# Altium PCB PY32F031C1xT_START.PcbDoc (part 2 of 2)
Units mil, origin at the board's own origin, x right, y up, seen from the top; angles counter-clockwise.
Board outline 1771.65 x 3929.06 mil, 2 copper layers (Top Layer, Bottom Layer), stack 21 mil thick; 137 components, 144 nets, 525 pads, 269 vias.
Unrouted connection lines stored in the file: 5.
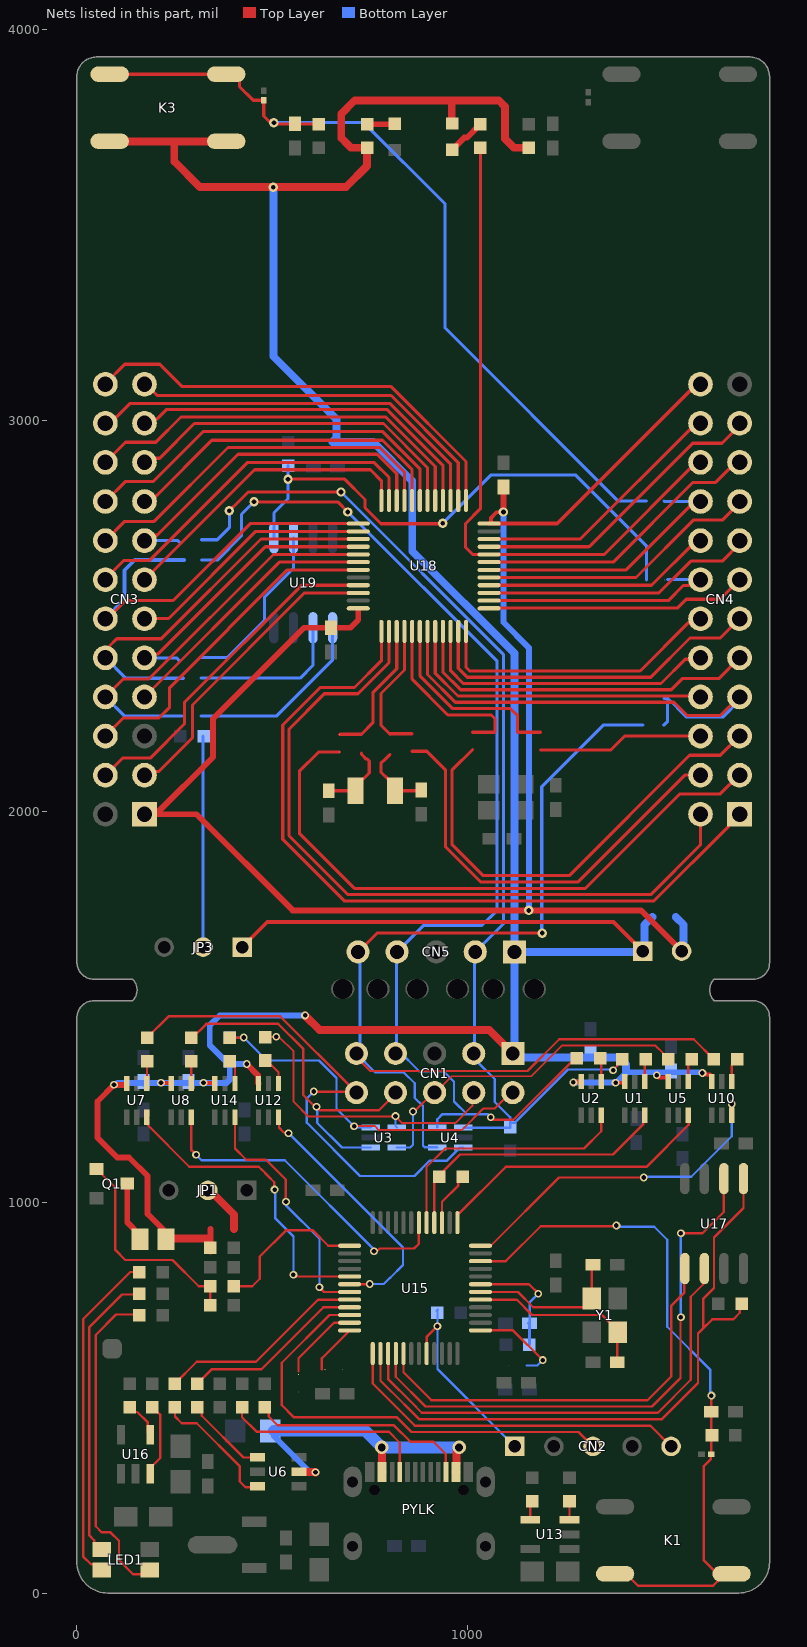
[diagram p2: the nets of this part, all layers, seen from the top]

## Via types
v1: diameter 19.68, hole 11.81, Top Layer to Bottom Layer, tented both sides, 116 vias
v2: diameter 24, hole 12, Top Layer to Bottom Layer, tented both sides, 99 vias
v3: diameter 19.68, hole 11.81, Top Layer to Bottom Layer, 42 vias
v4: diameter 35, hole 20, Top Layer to Bottom Layer, tented both sides, 8 vias
v5: diameter 30, hole 15, Top Layer to Bottom Layer, tented both sides, 2 vias
v6: diameter 40, hole 20, Top Layer to Bottom Layer, tented both sides, 2 vias

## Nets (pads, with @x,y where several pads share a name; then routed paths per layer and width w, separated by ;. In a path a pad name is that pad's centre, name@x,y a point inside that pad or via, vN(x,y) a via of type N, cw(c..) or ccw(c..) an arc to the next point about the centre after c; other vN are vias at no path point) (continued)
NetC32_1: C32.1 R54.2 Y3.2 | length 191.9
  Top Layer w8: C32.1@644,2052 Y3.2@713,2052 713,2064.8 729.67,2081.46 731.89,2081.46 747.91,2097.49 747.91,2128.31 743.22,2133 740,2133 728,2145 728,2149
NetC33_2: C33.2 R55.2 Y3.1 | length 186.4
  Top Layer w8: 800.54,2145 800.54,2144.54 789,2133 788.54,2133 777.52,2121.98 777.52,2100.14 796.2,2081.46 796.72,2081.46 813.39,2064.79 Y3.1@813.39,2052 879,2052 C33.2@881,2054
NetC34_2: C34.2 K3.3 K3.4 R56.1 R57.2 U21.1 | length 2162.7
  Top Layer w8: K3.4@85,3884.7 401.49,3884.7 415.99,3870.21 415.99,3853.01 450.72,3818.28 U21.1@478,3818.28 478,3778.17 492.11,3764.06 500.94,3764.06 v2(504,3761) ; v2@504,3767 513.02,3757.98 615.19,3757.98 R57.2@618,3760.8
  Bottom Layer w8: v2(504,3761) 734,3761 942,3553 942,3235.83 1384.84,2793 R56.1@1457.25,2793
NetCN4_3: CN4.3 R49.2 | length 1586.5
  Top Layer w8: R49.2@671.97,2150.97 617.97,2150.97 569,2102 569,1943 709.61,1802.39 1300.96,1802.39 1542.57,2044 1646,2044 1694,2092 CN4.3@1695,2092
NetCN4_4: CN4.4 R58.2 | length 1104.6
  Top Layer w8: R58.2@856.97,2152.97 895.03,2152.97 943.1,2104.9 943.1,1908.27 1032.37,1819 1056,1819 1282,1819 1555,2092 CN4.4@1595,2092
NetCN4_5: CN4.5 R59.2 | length 1180.8
  Top Layer w8: R59.2@1011.97,2156.97 959.1,2104.1 959.1,1914.9 1039,1835 1259,1835 1567,2143 1646,2143 CN4.5@1695,2192
NetCN4_6: CN4.6 R60.2 | length 423.9
  Top Layer w8: R60.2@1185.97,2155.97 1365.03,2155.97 1401.06,2192 CN4.6@1595,2192
NetJP3_2: JP3.2 R47.1 | length 539.2
  Bottom Layer w8: JP3.2@323,1652.81 R47.1@323,2192
NetLED1_2: LED1.2 R9.1 | length 846.1
  Top Layer w6: R9.1@160,710 157.67,712.33 100.33,712.33 48,660 48,171 63.8,155.2 85.86,155.2 107.53,133.53 107.53,84.16 143.82,47.87 175.08,47.87 LED1.2@186.02,58.82
NetLED1_3: LED1.3 R6.1 | length 884.3
  Top Layer w6: LED1.3@44.28,58.52 LED1.3@58.98,43.82 ; LED1.3@63.98,58.82 49.28,73.52 36.09,73.52 16,93.61 16,700.34 136.59,820.93 159.07,820.93 R6.1@160,820
NetLED1_4: LED1.4 R4.1 | length 755.1
  Top Layer w6: LED1.4@56.66,98.5 44.36,110.81 44.36,134.74 32,147.09 32,680.34 115.39,763.73 158.73,763.73 R4.1@160,765
NetLED_PB2_2: LED_PB2.2 R61.1 | length 98.9
  Top Layer w15: LED_PB2.2@960,3692 990.71,3722.71 997.72,3722.71 R61.1@1032,3756.99
NetLED_VDD*_1: LED_VDD*.1 R38.1 | length 70.4
  Top Layer w8: LED_VDD*.1@812,3757 LED_VDD*.1@813,3758
  Top Layer w15: R38.1@743,3757 LED_VDD*.1@812,3757
NetPYLK_A5: PYLK.A5 R1.2 | length 530.3
  Top Layer w6: R1.2@422.49,474.99 422.49,449.82 459.51,412.79 797.58,412.79 825.99,384.38 PYLK.A5@825.99,309.89
NetPYLK_B5: PYLK.B5 R3.1 | length 565.5
  Top Layer w6: R3.1@480,475 490.31,464.69 490.31,452.34 513.85,428.8 811.11,428.8 852.66,387.24 911.55,387.24 943.8,354.99 PYLK.B5@943.8,310.19
NetQ1_1: Q1.1 R19.1 R20.2 | length 559
  Top Layer w6: Q1.1@50,1084.8 51.97,1084.8 63.72,1073.06 63.72,1071.23 98.46,1036.49 98.46,877.34 123.86,851.94 244.45,851.94 311.61,784.78 R19.1@341.53,784.78 ; R20.2@341.52,735.88 R19.1@341.52,784.77
NetQ1_3: Q1.3 R15.1 | length 166.5
  Top Layer w6: Q1.3@125.49,1044.15 Q1.3@128.74,1047.4 ; R15.1@161.54,905 R15.1@161.54,910.91
  Top Layer w15: Q1.3@128.74,1047.4 128.74,948.28 161.54,915.49 R15.1@161.54,905
NetR2_1: R2.1 U1.4 | length 57.9
  Top Layer w6: U1.4@1452.23,1308.31 1452.23,1362.02 R2.1@1455.21,1365
NetR7_1: R7.1 U2.4 | length 57.8
  Top Layer w6: R7.1@1338.06,1365 1340.8,1362.27 U2.4@1340.8,1308.31
NetR10_1: R10.1 U5.4 | length 60.3
  Top Layer w6: U5.4@1563.66,1308.31 1563.66,1356.3 R10.1@1572.35,1365
NetR11_1: R11.1 U6.3 | length 332.9
  Top Layer w6: R11.1@250,475 250.77,474.23 250.77,451.69 268.41,434.05 306.8,434.05 416.24,324.61 416.24,285.87 431.63,270.48 459.74,270.48 U6.3@461.53,272.28
NetR12_1: R12.1 U6.1 | length 227.7
  Top Layer w6: R12.1@308.75,480 319.15,469.6 319.15,453.68 426,346.83 U6.1@471.97,346.83
NetR13_1: R13.1 U7.4 | length 59
  Top Layer w6: R13.1@173.55,1360 179.14,1354.41 U7.4@179.14,1303.31
NetR14_1: R14.1 U8.4 | length 60.8
  Top Layer w6: R14.1@280.94,1360.02 R14.1@290.82,1350.14 ; U8.4@292.86,1303.31 R14.1@292.86,1350.12
NetR18_1: R18.1 U10.4 | length 62.7
  Top Layer w6: U10.4@1675.08,1308.31 1675.08,1350.59 R18.1@1689.49,1365
NetR22_1: R22.1 U12.4 | length 75.3
  Top Layer w6: R22.1@481.63,1362.11 485.62,1362.11 515.71,1332.03 U12.4@515.71,1303.31
NetR24_2: R24.2 U13.4 | length 49.6
  Top Layer w6: U13.4@1160,187.5 1160,230 R24.2@1165,235
NetR25_2: R25.2 U13.3 | length 47.5
  Top Layer w6: U13.3@1260,187.5 R25.2@1260,235
NetR26_1: R26.1 U14.4 | length 62.8
  Top Layer w6: R26.1@391.2,1360.7 404.28,1347.62 U14.4@404.28,1303.31
NetR27_2: R27.2 U15.1 | length 237.7
  Top Layer w6: U15.1@1032.32,671.73 1115.61,671.73 v3(1191.46,595.88)
  Bottom Layer w6: R27.2@1150.03,582.03 1177.6,582.03 v3(1191.46,595.88)
NetR29_2: R29.2 U16.4 | length 96.1
  Top Layer w6: R29.2@135,475 147,463 154.44,463 181.5,435.94 181.5,411 U16.4@187.5,405
NetR30_2: R30.2 U16.3 | length 188.5
  Top Layer w6: U16.3@187.5,305 187.5,320 213.56,346.06 213.56,455.68 207,462.24 207,463 R30.2@195,475
NetR31_1: R31.1 U15.36 | length 129.6
  Top Layer w6: 626.21,571.75 626.21,600.26 U15.36@697.68,671.73
NetR33_1: R33.1 U15.35 | length 201.4
  Top Layer w6: 566.96,567.4 566.96,600.38 658,691.42 U15.35@697.68,691.42
NetR40_1: R40.1 R41.1 U19.1 | length 1390.7
  Top Layer w8: v2(540,2849.19) 684.68,2849.19 736.86,2797.01 736.86,2776.14 778,2735 935,2735 v2(936,2736)
  Bottom Layer w8: U19.1@504,2699 504,2763 540,2799 v2(540,2849.19) R40.1@540,2884 ; v2(936,2736) 1060,2860 1275,2860 1457.25,2677.75 R41.1@1457.25,2591
NetR42_1: R42.1 U19.2 | length 444.2
  Bottom Layer w8: R42.1@316.75,2393 385,2393 480,2488 480,2547 554,2621 U19.2@554,2699
NetR43_2: R43.2 U19.6 | length 396.6
  Bottom Layer w8: 317.03,2340.03 571.03,2340.03 604,2373 U19.6@604,2469
NetR44_2: R44.2 U19.5 | length 477.6
  Bottom Layer w8: R44.2@318.02,2243.03 510.03,2243.03 654,2387 U19.5@654,2469
NRST: CN4.7 R46.2 R53.2 U18.7 | length 1275.1
  Top Layer w8: U18.7@896.84,2459.68 896.84,2349.57 968.04,2278.36 1527.47,2278.36 1561.34,2244.5 1645.97,2244.5 1693.48,2292 CN4.7@1695,2292
  Bottom Layer w8: R53.2@1501.03,2220.03 1511,2230 1511,2281 ; R46.2@1502.03,2288.03 1511.97,2288.03 1558.64,2241.36 1653.32,2241.36 1695,2283.04 CN4.7@1695,2292
OSC32_IN: R49.1 R54.1 U18.3 | length 356.7
  Top Layer w8: R49.1@672,2195.75 673,2196.75 R54.1@728,2196.75 757,2225.75 757,2303 818.1,2364.1 U18.3@818.1,2459.68
OSC32_OUT: R55.1 R58.1 U18.4 | length 353.6
  Top Layer w8: U18.4@837.79,2459.68 837.79,2360.79 778,2301 778,2219.75 R55.1@801,2196.75 802,2197.75 R58.1@857,2197.75
OSC_IN: R48.2 R59.1 U18.5 | length 467.4
  Top Layer w8: U18.5@857.47,2459.68 857.47,2337.53 949,2246 1060,2246 1069.03,2236.97 R48.2@1069.03,2202.03 1068.75,2201.75 R59.1@1012,2201.75
OSC_OUT: R50.2 R60.1 U18.6 | length 507
  Top Layer w8: U18.6@877.16,2459.68 877.16,2346.62 961.78,2262 1109,2262 1127.34,2243.66 R50.2@1127.34,2201.56 1185.19,2201.56 R60.1@1186,2200.75
PA0: CN4.10 U18.10 | length 780.6
  Top Layer w8: U18.10@955.9,2459.68 955.9,2358.75 988.28,2326.36 1494.02,2326.36 1556.19,2388.53 1591.53,2388.53 CN4.10@1595,2392
PA1: CN4.11 U18.11 | length 885.5
  Top Layer w8: U18.11@975.58,2459.68 975.58,2364.98 998.2,2342.36 1467.7,2342.36 1568.18,2442.84 1645.84,2442.84 CN4.11@1695,2492
PA2: CN4.12 U18.12 | length 750.8
  Top Layer w8: U18.12@995.27,2459.68 995.27,2367.92 1004.82,2358.36 1440.6,2358.36 1563.71,2481.48 1584.48,2481.48 CN4.12@1595,2492
PA3: CN4.13 U18.13 | length 670.4
  Top Layer w8: U18.13@1054.8,2519.21 1535.86,2519.21 1558.55,2541.9 1644.9,2541.9 CN4.13@1695,2592
PA4: CN4.14 R41.2 U18.14 | length 646.9
  Top Layer w8: U18.14@1054.32,2538.42 1512.62,2538.42 1551.69,2577.49 1565.61,2577.49 1571.5,2583.38 1586.38,2583.38 CN4.14@1595,2592
  Bottom Layer w8: 1511,2592 CN4.14@1595,2592
PA5: CN4.15 U18.15 | length 700.9
  Top Layer w8: U18.15@1054.32,2558.1 1489.1,2558.1 1570.53,2639.53 1650.63,2639.53 1695,2683.9 CN4.15@1695,2692
PA6: CN4.16 U18.16 | length 588
  Top Layer w8: U18.16@1054.32,2577.79 1469.74,2577.79 1583.95,2692 CN4.16@1595,2692
PA7: CN4.17 U18.17 | length 723.6
  Top Layer w8: U18.17@1054.32,2597.47 1430.13,2597.47 1577.66,2745 1652,2745 1695,2788 CN4.17@1695,2792
PA8: CN3.20 U18.29 | length 1031.3
  Top Layer w8: CN3.20@73,2892 124.41,2943.41 201.7,2943.41 266.37,3008.08 790.02,3008.08 916.53,2881.57 U18.29@916.53,2794.32
PA9: CN3.19 U18.30 | length 896
  Top Layer w8: CN3.19@173,2892 183.52,2902.52 211.57,2902.52 300.42,2991.38 784.09,2991.38 896.84,2878.63 U18.30@896.84,2794.32
PA10: CN3.18 U18.31 | length 998.8
  Top Layer w8: CN3.18@73,2792 123.68,2842.68 194.5,2842.68 322.4,2970.58 782.26,2970.58 877.16,2875.68 U18.31@877.16,2794.32
PA11: CN3.17 U18.32 | length 859.1
  Top Layer w8: CN3.17@173,2792 187.88,2792 202.8,2806.92 203.59,2806.92 345.17,2948.5 781.71,2948.5 857.47,2872.75 U18.32@857.47,2794.32
PA12: CN3.16 U18.33 | length 962.2
  Top Layer w8: CN3.16@73,2692 122.07,2741.07 197.64,2741.07 386.68,2930.11 774.62,2930.11 837.79,2866.94 U18.33@837.79,2794.32
PA13: CN3.15 R51.2 U18.34 | length 918
  Top Layer w8: CN3.15@173,2692 183.52,2702.52 198.4,2702.52 201.51,2705.63 204.88,2705.63 412.19,2912.94 768.06,2912.94 818.1,2862.9 U18.34@818.1,2794.32
  Bottom Layer w8: CN3.15@173,2692 257.99,2692 262.99,2687
PA14: CN3.12 R52.2 U18.37 | length 1054.5
  Top Layer w8: CN3.12@73,2492 78.31,2492 124.87,2538.56 246.27,2538.56 442.98,2735.27 U18.37@719.68,2735.27
  Bottom Layer w10: CN3.12@73,2492 122,2541 122,2616 147.97,2641.97 R52.2@273.97,2641.97
PA15: CN3.11 U18.38 | length 639.3
  Top Layer w8: CN3.11@173,2492 173.58,2492.58 234.6,2492.58 457.6,2715.58 U18.38@719.68,2715.58
PB0: CN4.18 R56.2 U18.18 | length 706.5
  Top Layer w8: U18.18@1054.32,2617.16 1404.97,2617.16 1564.65,2776.84 1564.96,2776.84 1580.12,2792 CN4.18@1595,2792
  Bottom Layer w8: R56.2@1502.03,2793.03 1503.05,2792 CN4.18@1595,2792
PB1: CN4.19 U18.19 | length 746.4
  Top Layer w8: U18.19@1054.32,2636.84 1371.94,2636.84 1575.91,2840.81 1633.72,2840.81 1684.91,2892 CN4.19@1695,2892
PB2: CN4.20 R61.2 U18.20 | length 1743.9
  Top Layer w8: R61.2@1032,3696.99 1032,2773 994,2735 994,2675 1012.47,2656.53 U18.20@1054.32,2656.53 1349.01,2656.53 1584.48,2892 CN4.20@1595,2892
PB3: CN3.10 R43.1 U18.39 | length 1004.9
  Top Layer w8: CN3.10@73,2392 83.52,2402.52 83.52,2422.27 102.24,2440.98 215.88,2440.98 470.79,2695.9 U18.39@719.68,2695.9
  Bottom Layer w8: CN3.10@73,2392 125,2340 272.25,2340
PB4: CN3.9 R42.2 U18.40 | length 757.8
  Top Layer w8: CN3.9@173,2392 183.24,2402.24 208.27,2402.24 482.25,2676.21 U18.40@719.68,2676.21
  Bottom Layer w8: CN3.9@173,2392 254.73,2392 262.99,2383.74
PB5: CN3.8 R44.1 U18.41 | length 1013.2
  Top Layer w8: CN3.8@73,2292 119.25,2338.25 184.45,2338.25 502.73,2656.53 U18.41@719.68,2656.53
  Bottom Layer w8: CN3.8@73,2292 122,2243 268.25,2243
PB6: CN3.7 U18.42 | length 689.5
  Top Layer w8: CN3.7@173,2292 517.84,2636.84 U18.42@719.68,2636.84
PB7: CN3.6 U18.43 | length 852.6
  Top Layer w8: CN3.6@73,2192 73,2192.89 118.36,2238.25 209.6,2238.25 237.26,2265.92 237.26,2315.94 538.49,2617.16 U18.43@719.68,2617.16
PB8: CN3.4 U18.45 | length 880.3
  Top Layer w8: CN3.4@73,2092 116.5,2135.5 187.78,2135.5 275.36,2223.08 275.36,2278.33 574.82,2577.79 U18.45@719.68,2577.79
PB9: CN3.3 U18.46 | length 788.9
  Top Layer w8: CN3.3@173,2092 182.2,2101.2 209.31,2101.2 295.69,2187.58 295.69,2271.46 582.33,2558.1 U18.46@719.68,2558.1
PB10: CN4.21 U18.21 | length 775.1
  Top Layer w8: U18.21@1054.32,2676.21 1310.3,2676.21 1575.09,2941 1650.14,2941 1695,2985.86 CN4.21@1695,2992
PB11: CN4.22 U18.22 | length 663.3
  Top Layer w8: U18.22@1054.32,2695.9 1287.94,2695.9 1584.04,2992 CN4.22@1595,2992
PB12: CN3.24 U18.25 | length 1147.3
  Top Layer w8: CN3.24@73,3092 73,3093.6 122.51,3143.11 212.13,3143.11 269.52,3085.71 803.71,3085.71 995.27,2894.16 U18.25@995.27,2794.32
PB13: CN3.23 U18.26 | length 982.6
  Top Layer w8: CN3.23@173,3092 176.33,3092 205.27,3063.06 803.73,3063.06 975.58,2891.22 U18.26@975.58,2794.32
PB14: CN3.22 U18.27 | length 1061.5
  Top Layer w8: CN3.22@73,2992 85.18,2992 136.07,3042.89 800.46,3042.89 955.9,2887.45 U18.27@955.9,2794.32
PB15: CN3.21 U18.28 | length 926.8
  Top Layer w8: CN3.21@173,2992 183.52,3002.52 203.84,3002.52 228.21,3026.89 793.83,3026.89 936.21,2884.52 U18.28@936.21,2794.32
PF3: CN4.8 U18.8 | length 810.7
  Top Layer w8: U18.8@916.53,2459.68 916.53,2352.51 974.67,2294.36 1592.64,2294.36 CN4.8@1595,2292
PF4: CN4.9 U18.9 | length 915.3
  Top Layer w8: U18.9@936.21,2459.68 936.21,2355.81 981.66,2310.36 1519.91,2310.36 1548.51,2338.97 1641.97,2338.97 CN4.9@1695,2392
PF5: CN3.14 U18.35 | length 925.7
  Top Layer w8: CN3.14@73,2592 73,2594.42 119.15,2640.57 184.65,2640.57 435.36,2891.27 760.73,2891.27 798.42,2853.58 U18.35@798.42,2794.32
PF6: CN3.13 U18.36 | length 784.8
  Top Layer w8: CN3.13@173,2592 454.19,2873.19 750.94,2873.19 778.73,2845.4 U18.36@778.73,2794.32
PF8: CN4.1 U18.1 | length 2015.3
  Top Layer w8: U18.1@778.73,2459.68 778.73,2384.73 710.12,2316.12 622.12,2316.12 526.41,2220.41 526.41,1927.59 683.61,1770.39 1476.26,1770.39 1667.5,1961.63 1667.5,1964.5 CN4.1@1695,1992
PF9: CN4.2 U18.2 | length 1925
  Top Layer w8: U18.2@798.42,2459.68 798.42,2379.69 718.85,2300.12 632.74,2300.12 542.41,2209.79 542.41,1937.43 693.45,1786.39 1467.79,1786.39 1595,1913.6 CN4.2@1595,1992
PYLK_BOOT0: CN2.1 R28.1 U15.44 | length 514.7
  Top Layer w6: U15.44@894.53,612.68 894.53,655.07 v1(922.21,682.75)
  Bottom Layer w6: R28.1@923.26,724.4 920.49,721.63 922.21,719.9 v1(922.21,682.75) 922.21,572.79 CN2.1@1120,375
PYLK_KEY: C6.2 K1.1 K1.2 R16.1 U11.1 U15.10 | length 1798.2
  Top Layer w6: U15.10@1032.32,848.9 1097.14,848.9 1186.44,938.2 1378.2,938.2 v1(1380,940) ; K1.2@1376.55,49 1405.25,49 1435.5,18.75 1627.36,18.75 1639.02,30.41 1639.02,34.51 K1.1@1653.51,49 ; U11.1@1622.5,353.5 1622.5,403.5 C6.2@1622.5,463.5 1623,464 v1(1623,505) ; U11.1@1626.8,353.5 1625.06,353.5 1621.56,350 1621.56,342.45 1603,323.88 1603,191.77 1603,84.3 1638.3,49 K1.1@1653.51,49 ; K1.1@1674.55,49 K1.1@1653.51,49
  Bottom Layer w6: v1(1380,940) 1383.06,936.94 1392.62,936.94 1392.69,936.88 1476.64,936.88 1510,903.52 1510,681 1620.38,570.62 1620.38,507.62 v1(1623,505)
PYLK_NRST: C24.2 R36.1 U15.7 | length 298.5
  Top Layer w6: U15.7@1032.32,789.84 1156.36,789.84 v1(1180.4,765.8)
  Bottom Layer w6: C24.2@1158,690 1158,743.4 v1(1180.4,765.8)
  Bottom Layer w8: C24.2@1155.12,690 1157.6,687.52 R36.1@1157.6,635.62
PYLK_OSCIN: C19.2 U15.5 Y1.3 | length 465.6
  Top Layer w6: U15.5@1032.32,750.47 1125.05,750.47 1164.42,711.1 1343.11,711.1 1383.59,670.63 Y1.3@1383.59,666.69 1382.12,665.22 C19.2@1382.12,590
PYLK_OSCOUT: C25.2 U15.6 Y1.1 | length 399.8
  Top Layer w6: U15.6@1032.32,770.16 1127.99,770.16 1167.36,730.79 1297.03,730.79 1316.66,750.41 Y1.1@1316.66,753.31 1316.66,836.54 C25.2@1320.12,840
PYLK_SPI_CS: R35.1 U15.38 U17.1 | length 1667.6
  Top Layer w5: U15.38@776.42,612.68 776.42,543.62 837.66,482.38
  Top Layer w6: 837.66,482.38 875.95,444.09 1495.51,444.09 1588.88,537.47 1588.88,663.88 1601.77,676.77 ; R35.1@1700,740 1695.62,735.62 1695.62,716.69 1679.36,700.42 1625.42,700.42 1601.77,676.77 ; U17.1@1705,1060 1705,985 1629.69,909.69 1629.69,780.01 1601.77,752.09 1601.77,676.77
PYLK_SPI_MISO: U15.40 U17.2 | length 1437.2
  Top Layer w6: U15.40@815.79,612.68 815.79,553.3 891.8,477.3 1471,477.3 1543.9,550.2 1543.9,703.9 v1(1545,705) ; v1(1545,920) 1600,920 1655,975 U17.2@1655,1060
  Bottom Layer w6: v1(1545,705) v1(1545,920)
PYLK_SPI_MOSI: U15.41 U17.5 | length 1077.9
  Top Layer w6: U15.41@835.47,612.68 835.47,564.49 906.66,493.3 1459.42,493.3 1520.53,554.41 1520.53,735.09 1553.13,767.69 1553.13,828.13 U17.5@1555,830
PYLK_SPI_SCK: U15.39 U17.6 | length 1208.9
  Top Layer w6: U15.39@796.1,612.68 796.1,547.36 856.32,487.14 882.17,461.3 1486.07,461.3 1570.21,545.44 1570.21,758.06 1601.94,789.79 1601.94,826.94 U17.6@1605,830
SWD_SCK: CN2.5 U15.37 | length 906.8
  Top Layer w6: U15.37@756.73,612.68 756.73,535.75 864.48,428 1367,428 1467,428 CN2.5@1520,375
SWD_SDA: CN2.3 U15.34 | length 1172.2
  Top Layer w6: U15.34@697.68,711.1 646.11,711.1 524.05,589.04 524.05,480.71 555.57,449.2 818.75,449.2 855.95,412 1183,412 1283,412 CN2.3@1320,375
T_RESET: CN1.9 CN5.5 R18.2 R53.1 U4.4 | length 2815.6
  Top Layer w6: CN1.9@722.78,1362.78 750.2,1335.36 1152.91,1335.36 1233.99,1416.44 1578.06,1416.44 R18.2@1629.49,1365
  Top Layer w8: CN5.5@719.26,1639.56 767.7,1688 v2(1190,1688)
  Bottom Layer w6: CN1.9@715,1380 763.22,1331.78 836.02,1331.78 864.1,1303.69 864.1,1266.42 885.15,1245.37 885.15,1144.31 889.61,1139.85 921.09,1139.85 U4.4@921.54,1139.41
  Bottom Layer w8: CN1.9@715,1380 724.04,1389.04 CN5.5@724.04,1634.78 ; CN5.5@719.26,1639.56 CN5.5@724.15,1644.45 ; v2(1190,1688) 1189,1689 1189,2062.55 1346.45,2220 1448,2220
T_RESETa: U10.3 U15.12 | length 870.1
  Top Layer w6: U15.12@1032.32,888.27 1058.79,888.27 1233.47,1062.96 1321.53,1062.96 v1(1449.91,1062.96) ; v1(1674.82,1250.7) 1675.08,1250.44 U10.3@1675.08,1221.69
  Bottom Layer w6: v1(1449.91,1062.96) 1451.65,1064.7 1571.4,1064.7 1674.82,1168.11 v1(1674.82,1250.7)
T_RTCK_DTRa: U5.3 U15.13 | length 731.2
  Top Layer w6: U15.13@973.27,947.32 973.27,966.57 1096.7,1090 1456.99,1090 1565.18,1198.19 1565.18,1220.16 U5.3@1563.66,1221.69
T_RTCK_VCP_DTR: CN1.6 R10.2 U3.5 | length 868.3
  Top Layer w5: v1(859.81,1231.67) 863.24,1231.67 911.57,1280 CN1.6@915,1280 916.63,1280 958.49,1321.86 1161.73,1321.86 1240.3,1400.44 1479.98,1400.44 1500.35,1380.07 1500.35,1377 R10.2@1512.35,1365
  Bottom Layer w6: U3.5@818.46,1139.41 852.51,1139.41 859.81,1146.71 v1(859.81,1231.67)
T_TCK_SWCLK: CN1.7 CN5.4 R7.2 R52.1 U4.5 | length 2940.6
  Top Layer w6: CN1.7@820,1390 CN1.7@821.35,1391.35 ; v1(1058.5,1217.32) 1065.14,1210.69 1116.96,1210.69 1271.28,1365 R7.2@1278.06,1365
  Top Layer w8: v2(453,2791) 666.98,2791 v2(692.99,2764.99)
  Bottom Layer w6: CN1.7@822.5,1387.5 875.47,1334.53 937.65,1334.53 964.6,1307.57 964.6,1257.54 997.14,1225 ; U4.5@921.54,1190.59 921.54,1211.54 935,1225 997.14,1225 ; v1(1058.5,1217.32) 1050.82,1225 997.14,1225
  Bottom Layer w8: R52.1@318.75,2642 359,2642 421,2704 421,2759 v2(453,2791) ; v2(692.99,2764.99) 1074.75,2383.23 1074.75,1746.75 1035,1707 886,1707 CN5.4@819,1640 ; CN1.7@815,1380 817.79,1382.79 CN5.4@817.79,1638.1
T_TCK_SWCLKa: U2.3 U15.17 | length 668.1
  Top Layer w5: U15.17@894.53,947.32 894.53,1089.76 941.77,1137
  Top Layer w6: 941.77,1137 1047.62,1137 1297.43,1137 1341.41,1180.98 1341.41,1221.08 U2.3@1340.8,1221.69
T_TDI_VCP_TX: CN1.4 R22.2 U3.4 | length 783.1
  Top Layer w5: R22.2@481.63,1422.11 517.9,1422.11 554.54,1385.48 554.54,1256.62 592.29,1218.86 v1@815,1218.86 ; R22.2@481.63,1425.11 R22.2@483.13,1423.61 ; v1@815.02,1218.86 831.78,1202.11 967.76,1202.11 1011.56,1245.9 1011.56,1276.56 CN1.4@1015,1280
  Bottom Layer w5: v1@815.06,1219.94 815.06,1194 U3.4@818.46,1190.59
  other v1: 815,1220
  other v3: 509.96,1422.98
T_TDI_VCP_TXa: U12.3 U15.30 | length 672.4
  Top Layer w6: U12.3@515.71,1216.69 516.93,1215.47 516.93,1190.37 529.24,1178.06 539.56,1178.06 v1(541.31,1176.31) ; U15.30@697.68,789.84 748.02,789.84 v1(748.76,790.58)
  Bottom Layer w6: v1(541.31,1176.31) 834.09,883.53 834.09,838.92 801.56,806.38 800.71,806.38 784.91,790.58 v1(748.76,790.58)
T_TDO_SWO: CN1.10 R13.2 U4.3 | length 1321
  Top Layer w6: R13.2@179.66,1420.08 234.47,1474.9 520.1,1474.9 CN1.10@708.51,1286.49 ; v1(605.87,1282.75) 606.54,1282.08 704.1,1282.08 CN1.10@708.51,1286.49 ; CN1.10@715,1280 CN1.10@708.51,1286.49
  Bottom Layer w6: v1(605.87,1282.75) 587.83,1264.72 587.83,1203.17 724.14,1066.86 863.29,1066.86 902.42,1105.99 946.45,1105.99 979.88,1139.41 U4.3@988.46,1139.41 U4.3@986.15,1137.1
T_TDO_SWOa: U7.3 U15.29 | length 807.7
  Top Layer w6: U7.3@179.14,1216.69 179.14,1198.86 287.46,1090.54 465.08,1090.54 471.63,1084 472.01,1084 489,1067.01 489,1066.63 504.93,1050.7 504.93,1032.69 v1(505.62,1032) ; v1(553.88,814.33) 558.68,809.53 641.55,809.53 U15.29@697.68,809.53
  Bottom Layer w6: v1(505.62,1032) 506.95,1030.68 506.95,958.93 553.88,912 v1(553.88,814.33)
T_TMS_SWDIO: CN1.3 CN5.2 R2.2 R5.2 R51.1 U4.1 | length 2763.3
  Top Layer w6: CN1.3@1019.37,1366.19 CN1.3@1025.56,1360 ; v1@1371.62,1338.31 1382.21,1348.9 1382.21,1352 R2.2@1395.21,1365
  Top Layer w8: v2(390,2768) 414.53,2792.53 438.27,2816.27 v2(675.65,2816.27)
  Bottom Layer w6: U4.1@988.77,1190.29 R5.2@1109,1190.29 ; CN1.3@1015,1380 CN1.3@1017.13,1382.13 ; CN1.3@1023.59,1359.7 1068.86,1314.42 1068.86,1256.14 1108.1,1216.9 R5.2@1108.1,1203 ; R5.2@1109,1191 1108.1,1191.9 R5.2@1108.1,1203 ; v1(1371.43,1337.07) 1369.25,1339.25 1256.25,1339.25 1122,1205 1122,1204 1121,1203 R5.2@1108.1,1203
  Bottom Layer w8: R51.1@318.75,2694 359,2694 390,2725 v2(390,2768) ; v2(675.65,2816.27) 1091,2400.92 1091,1711.3 1017.13,1637.43 CN1.3@1017.13,1382.13
T_TMS_SWDIOa: R32.1 U1.3 U15.16 | length 723.8
  Top Layer w6: U15.16@914.21,947.32 R32.1@914.21,1067.37 ; R32.1@927.46,1064.37 927.46,1068.99 980.12,1121.65 1036.7,1121.65 1371.22,1121.65 1448.34,1198.77 1448.34,1217.8 U1.3@1452.23,1221.69
T_TMS_SWDIOa_OUT: R32.2 U15.15 | length 143.2
  Top Layer w6: U15.15@933.9,947.32 933.9,1000.64 975.82,1042.56 R32.2@975.82,1073.16
T_TRST_RTSa: U8.3 U15.18 | length 840.3
  Top Layer w6: U8.3@292.86,1216.69 292.86,1132.86 v1(304.82,1120.9) ; v1(759.92,874.35) 763.83,870.44 774.54,881.16 862.39,881.16 874.84,893.6 U15.18@874.84,947.32
  Bottom Layer w6: v1(304.82,1120.9) 318.81,1106.91 531.65,1106.91 759.92,878.64 v1(759.92,874.35)
T_TRST_VCP_RTS: CN1.8 R14.2 U3.1 | length 935
  Top Layer w6: R14.2@292.3,1420.1 295.54,1420.1 331.24,1455.8 515.25,1455.8 578.58,1392.47 578.58,1274.56 609.4,1243.73 v1(612.86,1243.73) 621.6,1235 772.67,1235 820,1282.33 CN1.8@820,1290
  Bottom Layer w6: v1(612.86,1243.73) 615,1241.6 615,1202.6 678.19,1139.41 U3.1@751.54,1139.41
T_VCP_RX: CN1.2 R23.1 R26.2 U3.3 | length 1000.9
  Top Layer w5: v1(708.97,1193.74) 710.23,1195 761.42,1195 772.45,1183.97 983.91,1183.97 1039.3,1239.36 1069.36,1239.36 CN1.2@1120,1290
  Top Layer w6: R26.2@391.2,1420.7 426.7,1420.7 v3(427,1421) ; R26.2@391.2,1431.85 R26.2@391.32,1431.97
  Bottom Layer w6: R23.1@391,1420 392,1421 v3(427,1421) 485.72,1362.28 619.26,1362.28 664.05,1317.5 664.05,1238.66 v1(708.97,1193.74) 708.23,1193 708.23,1191.77 750.36,1191.77 U3.3@751.54,1190.59
T_VCP_RXa: U14.3 U15.31 | length 636
  Top Layer w6: U14.3@404.28,1216.69 404.28,1137.29 433.27,1108.3 483.54,1108.3 534.4,1057.43 534.4,1001.38 v1(535,1000.78) ; v1(620.4,781.75) 631.99,770.16 U15.31@697.68,770.16
  Bottom Layer w6: v1(535,1000.78) 535,991.42 620.4,906.02 v1(620.4,781.75)
TVDD: C12.2 C13.2 C14.2 C15.2 CN1.1 CN5.1 JP2.1 JP3.1 K3.1 K3.2 LED_PB2.1 R15.2 R17.2 R23.2 R34.2 R37.1 R38.2 R39.1 R45.1 U1.6 U2.6 U5.6 U7.6 U8.6 U10.6 U12.6 U14.6 | length 8731.3
  Top Layer w6: U8.6@241.67,1303.31 U8.6@244.56,1306.2 ; U14.6@353.1,1303.31 U14.6@355.99,1306.2
  Top Layer w10: v1(215,1305) 239.98,1305 U8.6@241.67,1303.31 ; v3@325,1305 351.41,1305 U14.6@353.1,1303.31 ; JP3.1@423,1652 487,1716 1373,1716 JP2.1@1447,1642 ; v3(1377.88,1305.09) 1399.07,1305.09 1399.16,1305 1401.05,1306.89 U1.6@1401.05,1308.31 ; v1(1483.29,1324.06) 1488.61,1318.74 1512.47,1318.74 U5.6@1512.47,1308.31 ; v1@1608.68,1326.1 1618.91,1326.1 1623.9,1321.1 U10.6@1623.9,1308.31
  Top Layer w12: v1@1270.9,1306.9 U2.6@1289.01,1306.9
  Top Layer w15: v1(95,1300) 52.5,1257.5 52.5,1164.78 103.07,1114.2 133.42,1114.2 180.53,1067.09 180.53,969.95 220.52,929.96 220.52,912.95 R15.2@228.46,905 R15.2@230.24,906.78 ; v1@95.63,1299.37 U7.6@127.35,1299.37 ; 338.07,906.78 342.08,902.77 ; R17.2@342.08,874.02 342.08,902.77 ; 342.08,931.52 342.08,902.77 ; v3(434.28,1353.05) 462.84,1324.49 462.84,1305 U12.6@464.53,1303.31 ; v1(1270,1306) v1@1270.9,1306.9
  Top Layer w20: K3.2@85,3713 249,3713 ; R15.2@230.24,906.78 338.07,906.78 ; K3.1@383,3713 249,3713 ; v3(583.63,1477.38) 620.91,1440.1 1054.9,1440.1 CN1.1@1115,1380 ; LED_PB2.1@960,3759 959,3760 959,3818 ; R45.1@1156,3697 1118,3697 1095,3720 1095,3802 1079,3818 959,3818 ; 249,3713 249,3662 315,3596 v2(502.64,3596) 688,3596 742,3650 742,3696 R38.2@743,3697 701,3697 692.03,3705.97 676,3722 676,3783 711,3818 959,3818
  Bottom Layer w15: v1(95,1300) 98.79,1300 103.67,1304.88 C15.2@168.87,1304.88 ; C15.2@170,1303.74 C15.2@168.87,1304.88 ; v1@214.88,1304.88 C15.2@168.87,1304.88 ; v1(215,1305) v3(323.77,1305) 383,1305 391,1313 R23.2@391,1360 380.76,1360 340,1400.76 340,1452 365.38,1477.38 v3(583.63,1477.38) ; R23.2@391,1353.05 v3(434.28,1353.05) ; v1@1270.38,1305.62 v3@1377.36,1305.62 ; v3(1377.88,1305.09) 1379.15,1305.09 1381.49,1307.43 1382.09,1307.43 1406.58,1331.92 ; 1404.72,1331.92 1598.08,1331.92 v1(1600,1330)
  Bottom Layer w20: v2(502.64,3596) 502.64,3163.36 664,3002 664,2954.25 R39.1@653.75,2944 662,2944 758,2944 858,2844 858,2665.04 1119.26,2403.78 1119.26,1639.56 1449.44,1639.56 1452,1637 1452,1709 1472,1729 ; CN1.1@1118.94,1383.94 CN5.1@1118.94,1639.24 ; CN1.1@1122.04,1388.26 1143.46,1370 1386.9,1370 1404.72,1352.18 1404.72,1331.92
TVDD*: JP1.2 R34.1 | length 129
  Top Layer w20: JP1.2@335,1030 339.73,1030 402.08,967.65 402.08,931.52
TVDD_DISCHARGE_EN: R19.2 U15.25 | length 404.9
  Top Layer w6: R19.2@401.53,784.78 448.51,784.78 467.48,803.75 467.48,860.55 534.58,927.66 603.61,927.66 643,888.27 U15.25@697.68,888.27
USB_DM: R11.2 U15.32 | length 536.9
  Top Layer w6: R11.2@250,535 306.4,591.4 458.28,591.4 617.36,750.47 U15.32@697.68,750.47
USB_DP: R12.2 U15.33 | length 471.3
  Top Layer w6: R12.2@307.5,535 344.45,571.95 471.73,571.95 630.56,730.79 U15.33@697.68,730.79
VBUS_PYLK: F1.1 PYLK.A4 PYLK.A9 PYLK.B4 PYLK.B9 U6.5 | length 779.7
  Top Layer w10: PYLK.A4@774.81,309.89 PYLK.B9@786.62,309.89 ; PYLK.B4@963.78,309.88 PYLK.A9@975.6,309.88
  Top Layer w20: U6.5@568.15,310 568.98,309.17 609.58,309.17 v1(610.2,308.55) ; PYLK.B9@780.78,327.94 v4@780.78,371.72 ; PYLK.A9@971.19,329.42 v4@971.19,363.23
  Bottom Layer w15: F1.1@504.16,400.84 504.89,400.84 513.76,391.97 513.76,391.24 595.55,309.45 609.31,309.45 v1(610.2,308.55)
  Bottom Layer w30: F1.1@504.16,415 737.5,415 v4(780,372.5) v4(977.62,372.5)
VDD: C26.1 C27.2 CN3.1 CN4.24 JP2.2 R37.2 U18.24 U18.48 | length 4276.4
  Top Layer w10: U18.24@1054.32,2735.27 U18.24@1058.44,2735.27 ; v2(1091,2765) 1090.41,2764.41 1073.41,2764.41 1058.73,2749.73 1058.73,2735.56 U18.24@1058.44,2735.27 ; CN4.24@1595,3092 1585.43,3092 1228.7,2735.27 U18.24@1058.44,2735.27
  Top Layer w15: CN3.1@173,1992 CN3.1@202,1992 ; U18.48@719.78,2517 719.78,2488.78 700,2469 C26.1@650,2469 581,2469 348,2236 348,2138 CN3.1@202,1992 ; v2(1091,2765) 1091.5,2765.5 1091.5,2825.5 C27.2@1092,2826 ; JP2.2@1546.26,1642.74 1442.88,1746.12 1156.12,1746.12 v2(1156,1746) 1155.88,1746.12 551.88,1746.12 306,1992 CN3.1@202,1992
  Bottom Layer w15: v2(1091,2765) 1091,2483 1156,2418 v2(1156,1746)
  Bottom Layer w20: 1532,1729 1552,1709 JP2.2@1552,1637
pads on no net: PYLK. PYLK.A8 PYLK.B8 U15.42 U15.45

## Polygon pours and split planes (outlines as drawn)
GND on Bottom Layer "NONET_L-01_P-001" (solid, remove dead copper, pour order 3): 8.64,3929.06 1773.49,3929.06 1773.49,0 0,0
GND on Top Layer "NONET_L-01_P-001" (solid, remove dead copper, pour order 4): 8.64,3929.06 1773.49,3929.06 1773.49,0 0,0

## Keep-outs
Keep-Out Layer:
  lines w8: 0,78.74 ccw(c78.74,78.74) 78.74,0 1692.91,0 ccw(c1692.91,78.74) 1771.65,78.74 1771.65,1473.35 ccw(c1730,1473.35) 1730,1515 1630,1515 cw(c1657.5,1542.5) 1630,1570 1730,1570 ccw(c1730,1611.65) 1771.65,1611.65 1771.65,3855.75 1771.65,3879.06 ccw(c1721.65,3879.06) 1721.65,3929.06 1692.91,3929.06 78.74,3929.06 50,3929.06 ccw(c50,3879.06) 0,3879.06 0,3859.09 0,1615 ccw(c43.75,1613.75) 42.5,1570 142.5,1570 cw(c115,1542.5) 142.5,1515 42.5,1515 ccw(c43.75,1471.25) 0,1470 0,78.74 ; 215,1515 cw(c242.5,1542.5) 215,1570 565,1570 585,1570 cw(c557.5,1542.5) 585,1515 565,1515 215,1515 ; 1260,1515 cw(c1287.5,1542.5) 1260,1570 1280,1570 1560,1570 cw(c1532.5,1542.5) 1560,1515 1280,1515 1260,1515

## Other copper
Top Layer:
  pour cut-out: 1655,1370 1665,1370 1665,1360 1655,1360
  pour cut-out: 275,490 285,490 285,480 275,480
  pour cut-out: 275,525 285,525 285,515 275,515
  pour cut-out: 330,525 335.5,525 335.5,503 330,503
  pour cut-out: 330,490 340,490 340,480 330,480
  region net 5V_USB_CHGR: 385,235 395,245 420,245 465,200 510,200 530,180 660,180 660,120 515,120 515,140 490,165 435,165 400,200 385,215
  region net 3V3_PYLK: 240,315 290,315 310,295 355,295 360,290 360,250 345,235 345,165 362.5,147.5 355,140 293.39,140 293.39,153.49 305,165.1 305,230 280,255 240,255
  region net 3V3_PYLK: 1095,155 1105,165 1125,165 1135,155 1135,130 1140,125 1185,125 1190,120 1190,105 1185,100 1130,100 1095,135
  region net 3V3_USB_PYLK: 1227.5,120 1300,120 1315,135 1335,135 1345,125 1345,105 1330,90 1315,90 1290,65 1290,25 1225,25 1225,118.33
  pour cut-out: 390,495 400,495 400,485 390,485
  pour cut-out: 445,495 455,495 455,485 445,485
  pour cut-out: 1627.43,1037 1637.43,1037 1637.43,1027 1627.43,1027
  pour cut-out: 1675,1075 1685,1075 1685,1065 1675,1065

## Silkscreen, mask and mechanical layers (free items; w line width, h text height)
Top Overlay:
  drawing of 1057 lines, arcs and shapes, not listed
  text "USER_PB0" at 85,3605.66 h60
  text "NRST" at 1476.78,3595.64 h60
  text "PY32F031-START V2.0" at 656,3242.17 h65
  text "2025-05" at 809.95,3173.47 h65
  text "24" at 1573.96,3169 h50
  text "23" at 1682.96,3165.54 h50
  text "25" at 49.96,3164.54 h50
  text "26" at 147.96,3163.54 h50
  text "B13" at 390,3081.62 h50
  text "B12" at 246,3081.08 h50
  text "GND" at 1425,3074.62 h50
  text "VDD" at 1281,3074.08 h50
  text "B14" at 246,2979.57 h50
  text "B15" at 390,2980.1 h50
  text "B11" at 1281,2972.57 h50
  text "B10" at 1425,2973.1 h50
  text "A8" at 245.96,2880.3 h50
  text "A9" at 389.96,2880.3 h50
  text "B2" at 1281,2872.77 h50
  text "B1" at 1425,2872.77 h50
  text "A10" at 245.96,2778.89 h50
  text "A11" at 389.96,2778.36 h50
  text "B0" at 1281,2771.89 h50
  text "A7" at 1424.96,2771.36 h50
  text "A13" at 389.96,2677.91 h50
  text "A12" at 245.96,2677.38 h50
  text "A6" at 1280.96,2670.91 h50
  text "A5" at 1424.96,2670.91 h50
  text "F5" at 246,2578.11 h50
  text "F6" at 390,2578.11 h50
  text "A4" at 1280.96,2570.58 h50
  text "A3" at 1424.96,2571.11 h50
  text "A14" at 245.96,2475.6 h50
  text "A15" at 389.96,2476.14 h50
  text "A2" at 1280.96,2468.6 h50
  text "A1" at 1424.96,2468.6 h50
  text "B3" at 246,2376.23 h50
  text "B4" at 390,2375.69 h50
  text "A0" at 1280.96,2369.23 h50
  text "F4" at 1425,2368.69 h50
  text "B5" at 246,2275.89 h50
  text "B6" at 390,2275.89 h50
  text "F3" at 1281,2268.89 h50
  text "F2" at 1425,2268.36 h50
  text "B7" at 246,2173.84 h50
  text "BOOT0" at 390,2174.38 h50
  text "F1" at 1281,2166.84 h50
  text "F0" at 1425,2167.38 h50
  text "B8" at 246,2074.58 h50
  text "B9" at 390,2074.58 h50
  text "F10" at 1425,2067.58 h50
  text "F11" at 1281,2067.04 h50
  text "GND" at 246,1973.06 h50
  text "VDD" at 390,1972.53 h50
  text "F9" at 1281,1966.06 h50
  text "F8" at 1425,1966.06 h50
  text "1" at 1689,1893 h50
  text "2" at 1579.96,1892 h50
  text "48" at 151,1890.54 h50
  text "47" at 50,1888 h50
  text "GND" at 146,1725.54 h50
  text "BOOT0" at 259,1725.54 h50
  text "VDD*" at 426,1725 h50
  text "VDD*" at 1100,1710.51 h45
  text "NRST" at 630,1710.48 h45
  text "SWC" at 760,1710.48 h45
  text "GND" at 870,1710.48 h45
  text "SWD" at 985,1710.48 h45
  text "VDD*" at 1377,1698 h45
  text "VDD" at 1507,1698 h45
  text "IDD" at 1607,1624 h50
  text "NRST" at 670,1445.43 h40
  text "SWC" at 790,1445.43 h40
  text "GND" at 896.86,1445.43 h40
  text "SWD" at 996.31,1445.43 h40
  text "VDD*" at 1090,1445.46 h40
  text "DTR" at 896.86,1175.88 h40
  text "TX" at 996.31,1175.88 h40
  text "RX" at 1090,1175.88 h40
  text "SWO" at 670,1175.43 h40
  text "RTS" at 790,1175.43 h40
  text "VDD_SEL" at 513,1079.99 h45
  text "5V" at 190,1075.64 h60
  text "3V3" at 410,1075.64 h60
  text "VDD*" at 265,1075 h60
  text "5V_USB" at 49.98,563.82 h40 r90
  text "BT0" at 1076,424.54 h50
  text "VDD" at 1171,425 h50
  text "DIO" at 1277,424.54 h50
  text "CLK" at 1479,423.54 h50
  text "GND" at 1369,422.54 h50
  text "PY-LINK V2.0" at 693,392.47 h65
Bottom Overlay:
Mechanical 1:
  lines w6: 215,1515 565,1515 585,1515 ; 215,1570 565,1570 585,1570 ; 1260,1515 1280,1515 1560,1515 ; 1260,1570 1280,1570 1560,1570
  lines w8: 0,0 ccw(c0,1) 1,1 ; 215,1515 cw(c242.5,1542.5) 215,1570 ; 585,1515 ccw(c557.5,1542.5) 585,1570 ; 1260,1515 cw(c1287.5,1542.5) 1260,1570 ; 1560,1515 ccw(c1532.5,1542.5) 1560,1570

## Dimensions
1856.64,2.11 to 1850.64,3930.11 on Mechanical 1
42.5,1570 to 78.74,3929.06 on Mechanical 1
78.74,0 to -5,1505 on Mechanical 1
0,0 to 1770,-60 on Mechanical 1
